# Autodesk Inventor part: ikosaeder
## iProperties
Created: 2007-01
Part Number: ikosaeder
Cost Center: 0 kg
Material: S235JRG2 (1.0038)
Document SubType Name: Modeling
Designer: M. Fiedler
Manufacturer: Standard
Standards Organization: Custom
Einheit: Stück
Ersatzteil: ET AB VT
Grundoberfläche: Rz6.3
WSK a+: 0
WSK a-: -0.1
WSK i+: +0.1
WSK i-: 0
a: 52,533 mm
SaveDate: 2007-01-25
SaveTime: 20:45
FileName: ikosaeder Master
Masse: 0 kg
Author: M. Fiedler
